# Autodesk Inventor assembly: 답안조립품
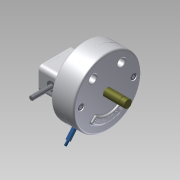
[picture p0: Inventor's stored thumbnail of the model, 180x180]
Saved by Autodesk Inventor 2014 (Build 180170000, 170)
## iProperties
Created: 2015-04
Part Number: 답안조립품
Document SubType Name: Assembly
Designer: Administrator
Mass: 3964.99 g
Surface Area: 3333.71 cm^2
Volume: 1140.85 cm^3
Density: 3.47547 g/cm^3
Author: Administrator
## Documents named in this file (15)
- C:\Documents and Settings\Administrator\바탕 화면\350406V1021\답안조립품.iam
- C:\Documents and Settings\Administrator\바탕 화면\350406V1021\본체.ipt
- C:\Documents and Settings\Administrator\바탕 화면\350406V1021\커버.ipt
- C:\Documents and Settings\Administrator\바탕 화면\350406V1021\베어링62_22.ipt
- C:\Documents and Settings\Administrator\바탕 화면\350406V1021\커버2.ipt
- C:\Documents and Settings\Administrator\바탕 화면\350406V1021\축.ipt
- C:\Documents and Settings\Administrator\바탕 화면\350406V1021\멈춤링.ipt
- C:\Documents and Settings\Administrator\바탕 화면\350406V1021\슬라이더2.ipt
- C:\Documents and Settings\Administrator\바탕 화면\350406V1021\슬라이더.ipt
- C:\Documents and Settings\Administrator\바탕 화면\350406V1021\M 5 x 12.ipt
- C:\Documents and Settings\Administrator\바탕 화면\350406V1021\M 10 x 35.ipt
- C:\Documents and Settings\Administrator\바탕 화면\350406V1021\평행핀.ipt
- C:\Documents and Settings\Administrator\바탕 화면\350406V1021\부시.ipt
- C:\Documents and Settings\Administrator\바탕 화면\350406V1021\슬라이더3.ipt
- C:\Documents and Settings\Administrator\바탕 화면\350406V1021\스프링 - [가변].ipt
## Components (5 placed, 3 different names)
1. M 5 x 12:1
2. M 5 x 12:2
3. M 10 x 35:1
4. M 10 x 35:2
5. KS B 1320 B B 5 x  20:1 — 플러쉬:2
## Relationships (1: Flush 1)
- 플러쉬:2 [Flush]: KS B 1320 B B 5 x  20:1
